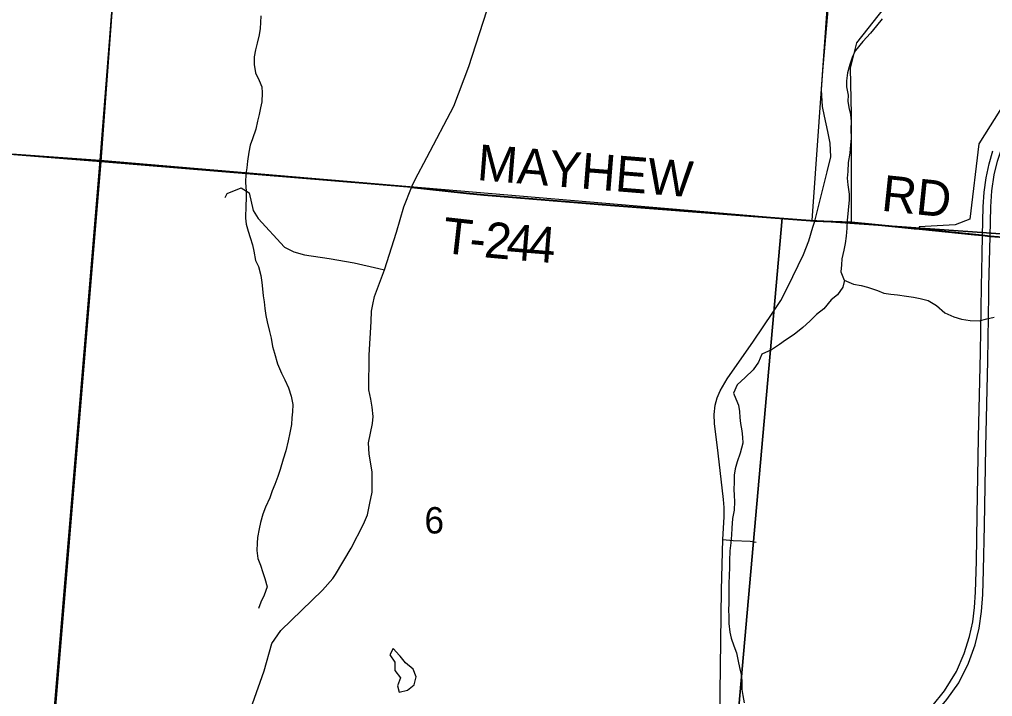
# Model space of a CAD drawing. Extents: x 0 to 34, y 0 to 22.
# Drawn here: x 26.174 to 27.717, y 19.082 to 20.156 of the extents above; entities that cross this region are included whole.
import ezdxf

# ---------------------------------------------------------------- set-up
doc = ezdxf.new("R2010")
doc.units = 0
for name, color, linetype in [('GM_X_Corporation', 7, 'Continuous'), ('GM_X_County_Road', 7, 'Continuous'), ('GM_X_Minor_Lake', 7, 'Continuous'), ('GM_X_Minor_River', 7, 'Continuous'), ('GM_X_Section_Text', 7, 'Continuous'), ('GM_X_State_Route', 7, 'Continuous'), ('GM_X_Township_Road', 7, 'Continuous'), ('GM_X_Township_Road_Text', 7, 'Continuous')]:
    doc.layers.add(name, color=color, linetype=linetype)

msp = doc.modelspace()

# ---------------------------------------------------------------- linework, layer by layer
at = {"layer": 'GM_X_Corporation'}
for points in [[(26.3743, 20.9), (23.5167, 20.9), (23.5167, 20.1476), (23.8215, 20.1257), (24.2296, 20.084), (24.3889, 20.0736), (25.117, 20.0172), (25.2916, 20.0037), (25.482, 19.99), (25.7174, 19.9778), (26.3029, 19.931), (26.3351, 20.3683)], [(26.378, 20.9), (25.3573, 20.9), (25.2979, 20.0049), (26.302, 19.9328)], [(26.7674, 20.9), (26.378, 20.9), (26.302, 19.9328), (27.3834, 19.8411), (27.4311, 19.8373), (27.5018, 20.8365)], [(27.5018, 20.8365), (28.5465, 20.7695), (28.4917, 19.7627), (28.3876, 19.7694), (27.4311, 19.8373)], [(26.302, 19.9328), (26.2267, 19.0272), (25.2286, 19.1118), (25.2979, 20.0049)], [(27.3834, 19.8411), (27.2938, 18.8276), (26.2169, 18.8995), (26.2267, 19.0272), (26.302, 19.9328)], [(27.4311, 19.8373), (28.3876, 19.7694), (28.2889, 18.7562), (27.2938, 18.8276), (27.3834, 19.8411)]]:
    msp.add_lwpolyline(points, close=True, dxfattribs=at)
for points in [[(30.3167, 20.9), (26.3743, 20.9), (26.3351, 20.3683), (26.3029, 19.931), (26.7956, 19.89), (26.8828, 19.8806), (26.9103, 19.8778), (27.1108, 19.8614), (27.3234, 19.8454), (27.4349, 19.8368), (27.4932, 19.8346), (27.6007, 19.8241), (27.7009, 19.814), (27.713, 19.8126), (27.7479, 19.8098)], [(27.7377, 20.0262), (27.6953, 19.9588), (27.6811, 19.8396), (27.6576, 19.8303), (27.6007, 19.8271), (27.6007, 19.8241), (27.5679, 19.8271), (27.4932, 19.8346), (27.4932, 19.8804), (27.4932, 20.0054), (27.4919, 20.0789), (27.502, 20.1192), (27.5714, 20.208), (27.6201, 20.2028), (27.6229, 20.2429), (27.4708, 20.2643), (27.4734, 20.3021), (27.624, 20.2809), (27.9533, 20.2636)], [(26.1825, 18.4635), (26.1926, 18.5708), (26.207, 18.8068), (26.2271, 19.0168), (26.2277, 19.0233), (26.2281, 19.0286), (26.3029, 19.931), (25.7174, 19.9778), (25.482, 19.99), (25.2916, 20.0037), (25.117, 20.0172), (24.3889, 20.0736), (24.2296, 20.084), (23.8215, 20.1257), (23.5167, 20.1476), (23.5167, 14.1), (25.8273, 14.1), (25.8671, 14.5774), (25.9626, 15.7291)], [(27.7479, 19.8098), (27.713, 19.8126), (27.7009, 19.814), (27.6007, 19.8241), (27.4932, 19.8346), (27.4349, 19.8368), (27.3234, 19.8454), (27.1108, 19.8614), (26.9103, 19.8778), (26.8828, 19.8806), (26.7956, 19.89), (26.3029, 19.931), (26.2281, 19.0286)]]:
    msp.add_lwpolyline(points, dxfattribs=at)
at = {"layer": 'GM_X_County_Road'}
msp.add_line((26.7958, 19.8894), (26.797, 19.8922), dxfattribs=at)
for points in [[(26.797, 19.8922), (26.8016, 19.9024), (26.8198, 19.9372), (26.8631, 20.0188), (26.8868, 20.0815), (26.9614, 20.3123), (26.962, 20.314), (26.9705, 20.3306), (26.987, 20.363)], [(26.7531, 19.759), (26.772, 19.8187), (26.7837, 19.8587), (26.7958, 19.8894)], [(26.5437, 19.0706), (26.5623, 19.1231), (26.574, 19.1666), (26.5887, 19.187), (26.6545, 19.2509), (26.6708, 19.2696), (26.6752, 19.276), (26.7002, 19.3178), (26.7195, 19.3558), (26.7259, 19.3706), (26.7294, 19.389), (26.7331, 19.4066), (26.7334, 19.4186), (26.7334, 19.4385), (26.7286, 19.4669), (26.7277, 19.4849), (26.7338, 19.5151), (26.7347, 19.5267), (26.7336, 19.5414), (26.7314, 19.5541), (26.7283, 19.5685), (26.7286, 19.6238), (26.7317, 19.6769), (26.7324, 19.6935), (26.7342, 19.7041), (26.7373, 19.7169), (26.7531, 19.759)]]:
    msp.add_lwpolyline(points, dxfattribs=at)
at = {"layer": 'GM_X_Minor_Lake'}
for points in [[(26.7779, 19.1461), (26.7767, 19.1476), (26.7668, 19.1583), (26.7615, 19.1484), (26.7695, 19.1366), (26.7691, 19.1238), (26.7781, 19.112), (26.7736, 19.0995), (26.7762, 19.0892), (26.7895, 19.0926)], [(26.7895, 19.0926), (26.8001, 19.101), (26.8031, 19.1135), (26.7982, 19.1256), (26.7861, 19.1359), (26.7779, 19.1461)]]:
    msp.add_lwpolyline(points, dxfattribs=at)
at = {"layer": 'GM_X_Minor_River'}
for points in [[(26.5568, 20.1618), (26.5564, 20.1512), (26.5556, 20.1418), (26.554, 20.1319), (26.5509, 20.1183), (26.5481, 20.1081), (26.5462, 20.0967), (26.5461, 20.0846), (26.5483, 20.0716), (26.5542, 20.0591), (26.5583, 20.0492), (26.559, 20.0397), (26.5582, 20.0257), (26.5562, 20.0158), (26.5543, 20.0052), (26.5515, 19.9946), (26.5488, 19.9821), (26.5434, 19.9666), (26.5399, 19.9568), (26.5376, 19.9454), (26.5356, 19.9314), (26.5344, 19.9208), (26.5328, 19.9113), (26.5323, 19.8973), (26.5334, 19.8836), (26.5337, 19.8723), (26.5332, 19.8613), (26.5323, 19.8408), (26.5334, 19.8313), (26.5367, 19.8203), (26.5397, 19.8104), (26.5438, 19.7986), (26.5456, 19.7884), (26.5485, 19.7739), (26.553, 19.7644), (26.5567, 19.75), (26.5585, 19.739), (26.5596, 19.7287), (26.5606, 19.7177), (26.5621, 19.7082), (26.5631, 19.6976), (26.5646, 19.6866), (26.5668, 19.6767), (26.5708, 19.6615), (26.5734, 19.6505), (26.5752, 19.6372), (26.5785, 19.627), (26.5834, 19.6102), (26.5897, 19.5954), (26.5949, 19.5848), (26.6009, 19.5718), (26.605, 19.5589), (26.6075, 19.5456), (26.6071, 19.5339), (26.6062, 19.5244), (26.6054, 19.5138), (26.6027, 19.5005), (26.5999, 19.4876), (26.5964, 19.4721), (26.5922, 19.4589), (26.5875, 19.4426), (26.5836, 19.4312), (26.579, 19.4184), (26.5748, 19.4085), (26.5709, 19.3976), (26.5644, 19.3824), (26.5602, 19.3718), (26.5563, 19.3586), (26.5539, 19.3484), (26.5516, 19.3347), (26.5511, 19.3253), (26.5503, 19.3139), (26.5521, 19.3014), (26.5562, 19.2907), (26.5599, 19.2793), (26.5629, 19.2694), (26.5669, 19.2561), (26.5623, 19.2429), (26.5569, 19.2319), (26.5531, 19.2217)], [(27.5422, 20.1572), (27.533, 20.1462), (27.5235, 20.1346), (27.5113, 20.121), (27.4998, 20.107), (27.4952, 20.0972), (27.491, 20.0847), (27.4871, 20.0715), (27.4855, 20.059), (27.4854, 20.0495), (27.488, 20.0362), (27.4875, 20.0263), (27.4894, 20.0165), (27.4919, 20.0054), (27.493, 19.9944), (27.4925, 19.9827), (27.4928, 19.9671), (27.492, 19.9573), (27.4908, 19.944), (27.488, 19.9292), (27.4875, 19.9148), (27.4867, 19.9046), (27.4874, 19.8936), (27.4896, 19.8792), (27.4895, 19.8693), (27.4887, 19.8594), (27.4875, 19.8477), (27.4863, 19.8378), (27.4862, 19.8249), (27.4849, 19.8124), (27.4833, 19.8007), (27.4814, 19.7901), (27.4783, 19.7765), (27.4774, 19.767), (27.4766, 19.756), (27.4818, 19.7427), (27.4965, 19.7365), (27.5086, 19.7342), (27.5188, 19.7318), (27.5347, 19.726), (27.5449, 19.7222), (27.5558, 19.7206), (27.5664, 19.7194), (27.5804, 19.7174), (27.5917, 19.7158), (27.6023, 19.7138), (27.6148, 19.7103), (27.628, 19.7023), (27.6415, 19.6908), (27.6559, 19.6846), (27.668, 19.6808), (27.6816, 19.6788), (27.6959, 19.6783), (27.7081, 19.6812), (27.7198, 19.6838)], [(27.4825, 19.7424), (27.4795, 19.7313), (27.4711, 19.7196), (27.4612, 19.7117), (27.4493, 19.6974), (27.4379, 19.6884), (27.4273, 19.6774), (27.4162, 19.6676), (27.4025, 19.6564), (27.3888, 19.6477), (27.3793, 19.6406), (27.3664, 19.6323), (27.3512, 19.6252), (27.3458, 19.6127), (27.3374, 19.6007), (27.3249, 19.5882), (27.3123, 19.5769), (27.3065, 19.5637), (27.3099, 19.5542), (27.314, 19.5443), (27.3158, 19.5344), (27.3165, 19.5249), (27.3176, 19.5151), (27.3197, 19.5037), (27.3208, 19.4938), (27.3211, 19.484), (27.3169, 19.4681), (27.3122, 19.4544), (27.3091, 19.4435), (27.3072, 19.4336), (27.3071, 19.4219), (27.307, 19.4112), (27.3073, 19.401), (27.308, 19.3915), (27.3072, 19.3779), (27.3048, 19.3646), (27.3039, 19.3494), (27.3031, 19.3388), (27.3019, 19.3263), (27.3007, 19.3134), (27.2998, 19.2975), (27.3001, 19.288), (27.2993, 19.2732), (27.2988, 19.2626), (27.2987, 19.252), (27.299, 19.2418), (27.299, 19.2304), (27.2985, 19.2194), (27.2988, 19.2099), (27.2987, 19.1981), (27.3005, 19.1845), (27.3028, 19.175), (27.3068, 19.1628), (27.3113, 19.1518), (27.3139, 19.1385), (27.3157, 19.1282), (27.3186, 19.1172), (27.3197, 19.1074), (27.3196, 19.0937), (27.3211, 19.0842), (27.3232, 19.0721)]]:
    msp.add_lwpolyline(points, dxfattribs=at)
at = {"layer": 'GM_X_State_Route'}
for p, q in [((27.4323, 19.8268), (27.4351, 19.8363)), ((27.7114, 19.7325), (27.7133, 19.8121))]:
    msp.add_line(p, q, dxfattribs=at)
for points in [[(27.4351, 19.8363), (27.4549, 19.9142), (27.4606, 19.9384), (27.4598, 19.9597), (27.4561, 19.9782), (27.4508, 20.0025), (27.4472, 20.0181), (27.4458, 20.0447), (27.4477, 20.0745), (27.4747, 20.3831), (27.4763, 20.4068), (27.4782, 20.4239), (27.48, 20.4369), (27.4828, 20.448), (27.4869, 20.4597), (27.4963, 20.4829), (27.5039, 20.5023), (27.5068, 20.5138), (27.5088, 20.5248), (27.5096, 20.5372), (27.5085, 20.5533), (27.5055, 20.574), (27.501, 20.5975)], [(27.7133, 19.8121), (27.7141, 19.859), (27.7161, 19.8843), (27.7199, 19.9098), (27.7248, 19.9314), (27.732, 19.9519), (27.7389, 19.97), (27.7473, 19.988), (27.7577, 20.0041), (27.7705, 20.0224), (27.7843, 20.0388), (27.7978, 20.0521), (27.8163, 20.0689), (27.833, 20.0816), (27.8528, 20.097), (27.8732, 20.1115), (27.8991, 20.1306)], [(27.7012, 19.8134), (27.7023, 19.8589), (27.7036, 19.8823), (27.7071, 19.905), (27.7118, 19.927), (27.7173, 19.9477)], [(27.2846, 19.0478), (27.2873, 19.2517), (27.2895, 19.3313), (27.2913, 19.3671), (27.2916, 19.3819), (27.2905, 19.3947), (27.2821, 19.4684), (27.2763, 19.5155), (27.2757, 19.5297), (27.277, 19.5443), (27.2805, 19.556), (27.2851, 19.567), (27.2962, 19.5864), (27.3382, 19.6461), (27.3686, 19.6916), (27.3812, 19.7104), (27.392, 19.7311), (27.4172, 19.7832), (27.4258, 19.805), (27.4323, 19.8268)], [(27.6997, 19.7326), (27.7008, 19.7834), (27.7012, 19.8134)], [(27.4588, 18.9662), (27.4595, 18.9664), (27.4998, 18.9775), (27.5357, 18.991), (27.5651, 19.0059), (27.595, 19.0259), (27.6217, 19.05), (27.6448, 19.0777), (27.6634, 19.1041), (27.6789, 19.1351), (27.6893, 19.1642), (27.696, 19.1907), (27.6996, 19.2171), (27.7018, 19.2443), (27.7026, 19.2826), (27.7041, 19.3538), (27.7065, 19.4779), (27.7095, 19.6149), (27.7111, 19.7195), (27.7114, 19.7325)], [(27.6212, 19.0673), (27.6408, 19.0914), (27.66, 19.1223), (27.6722, 19.1504), (27.6806, 19.1774), (27.6857, 19.2009), (27.6883, 19.2234), (27.69, 19.2476), (27.6914, 19.297), (27.6926, 19.3698), (27.6949, 19.4932), (27.6979, 19.6279), (27.6997, 19.7326)]]:
    msp.add_lwpolyline(points, dxfattribs=at)
at = {"layer": 'GM_X_Township_Road'}
for p, q in [((27.4351, 19.8363), (27.4747, 19.8348)), ((27.5733, 19.8263), (27.593, 19.8243))]:
    msp.add_line(p, q, dxfattribs=at)
for points in [[(26.5005, 19.8735), (26.5036, 19.8799), (26.5258, 19.8893), (26.5384, 19.8813), (26.5446, 19.853), (26.5525, 19.8403), (26.5945, 19.795), (26.609, 19.7876), (26.626, 19.783), (26.6649, 19.777), (26.7048, 19.7703), (26.7441, 19.7611), (26.7531, 19.759)], [(26.7531, 19.759), (26.772, 19.8187), (26.7837, 19.8587), (26.7958, 19.8894)], [(26.7958, 19.8894), (26.883, 19.88), (26.9105, 19.8773), (27.111, 19.8609), (27.3236, 19.8449), (27.4351, 19.8363)], [(27.4747, 19.8348), (27.4934, 19.8341), (27.5733, 19.8263)], [(27.593, 19.8243), (27.6009, 19.8236), (27.6885, 19.8145), (27.7012, 19.8134), (27.7133, 19.8121), (27.7431, 19.8097)], [(27.2895, 19.3313), (27.306, 19.3298), (27.3329, 19.3287), (27.342, 19.3269)]]:
    msp.add_lwpolyline(points, dxfattribs=at)

# ---------------------------------------------------------------- texts
at = {"layer": 'GM_X_Section_Text'}
msp.add_text('6', height=0.0419, rotation=0, dxfattribs=at).set_placement((26.8162, 19.3409))
at = {"layer": 'GM_X_Township_Road_Text'}
for s, height, rotation, p in [('MAYHEW', 0.05682, 355.3966, (26.8986, 19.9015)), ('RD', 0.05682, 354.0783, (27.5394, 19.853)), ('T', 0.0568, 353.5278, (26.8427, 19.7863)), ('2', 0.0568, 354.8882, (26.9096, 19.7791)), ('4', 0.0568, 355.2698, (26.9449, 19.7759)), ('4', 0.0568, 355.3691, (26.9799, 19.773)), ('-', 0.0568, 354.465, (26.8859, 19.7814))]:
    msp.add_text(s, height=height, rotation=rotation, dxfattribs=at).set_placement(p)

doc.saveas('drawing.dxf')
